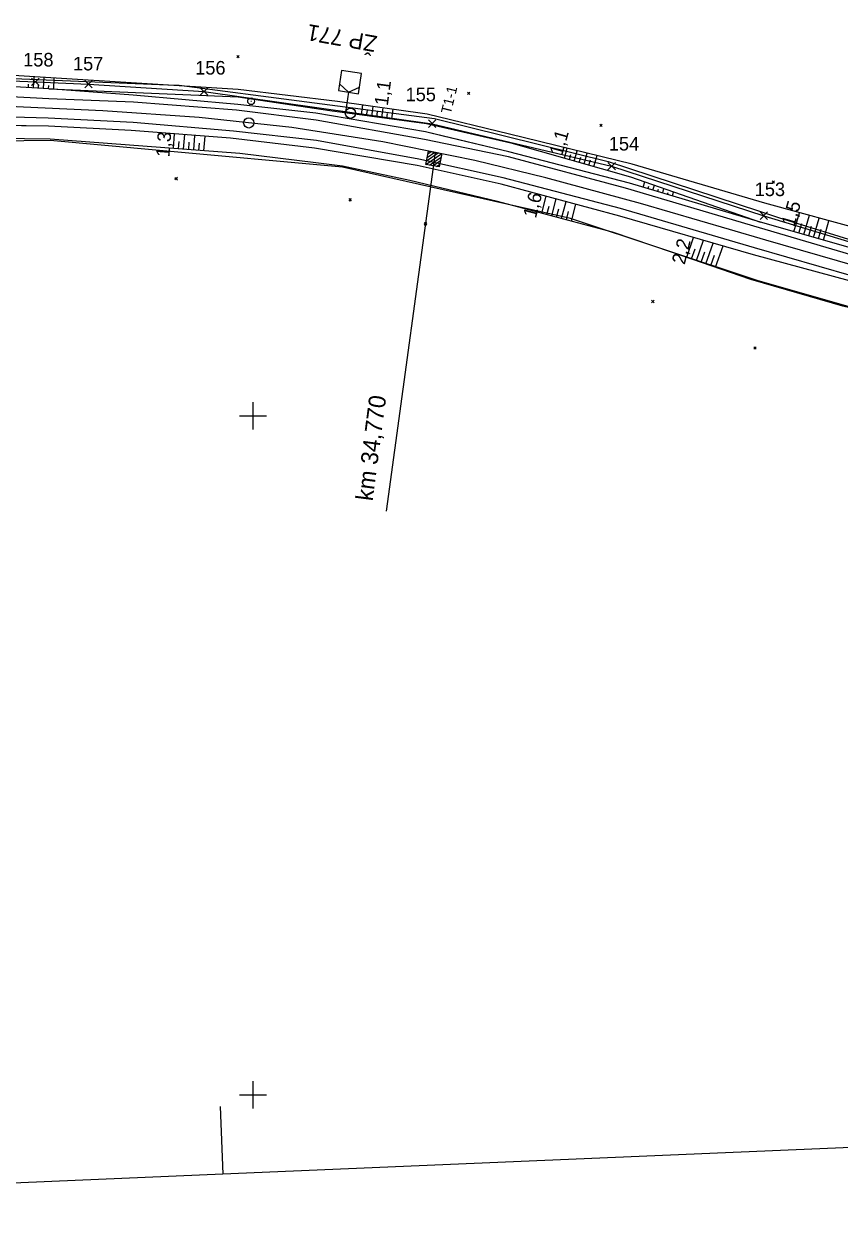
# Model space of a CAD drawing. Extents: x -806456 to -805395, y -1150847 to -1150506.
# Drawn here: x -805633.7 to -805513.6, y -1150820.6 to -1150642.3 of the extents above; entities that cross this region are included whole.
import ezdxf

# ---------------------------------------------------------------- set-up
doc = ezdxf.new("R2010")
doc.units = 0
for name, color, linetype in [('0381KM032-037P - Vrstva 1', 7, 'Continuous'), ('0381KM032-037P - Vrstva 3', 7, 'Continuous'), ('0381KM032-037P - Vrstva 4', 7, 'Continuous'), ('0381KM032-037P - Vrstva 48', 7, 'Continuous'), ('0381KM032-037P - Vrstva 49', 7, 'Continuous'), ('0381KM032-037P - Vrstva 7', 7, 'Continuous'), ('Default', 7, 'Continuous'), ('formát', 7, 'Continuous'), ('hran DP - hran DP', 7, 'Continuous'), ('krizky_1000 - Vrstva 1', 7, 'Continuous'), ('PSR_C2_2_Lomove_body_Vimperk - Vrstva 60', 7, 'Continuous'), ('PSR_C2_2_trasa_Vimperk - Kabelová trasa', 7, 'Continuous'), ('vyt_sit - ohrožené', 7, 'Continuous')]:
    doc.layers.add(name, color=color, linetype=linetype)

msp = doc.modelspace()

# ---------------------------------------------------------------- linework, layer by layer
at = {"layer": '0381KM032-037P - Vrstva 1'}
for points in [[(-805607.93, -1150656.05), (-805622.11, -1150655.05), (-805635.9, -1150654.45), (-805647.61, -1150654.06)], [(-805567.32, -1150662.37), (-805580.89, -1150659.62), (-805594.29, -1150657.54), (-805607.93, -1150656.05)], [(-805529.81, -1150672.54), (-805542.91, -1150668.73), (-805556.85, -1150664.92), (-805567.32, -1150662.37)], [(-805499.4, -1150681.08), (-805511.35, -1150677.89), (-805524.48, -1150674.12), (-805529.81, -1150672.54)]]:
    msp.add_lwpolyline(points, dxfattribs=at)
at = {"layer": '0381KM032-037P - Vrstva 3'}
for p, q in [((-805573.17, -1150661.19), (-805580.37, -1150714.04)), ((-805574.52, -1150662.97), (-805572.18, -1150661.37)), ((-805574.42, -1150662.44), (-805572.71, -1150661.27)), ((-805574.32, -1150661.92), (-805573.23, -1150661.17)), ((-805574.23, -1150661.4), (-805573.75, -1150661.08)), ((-805574, -1150663.06), (-805572.28, -1150661.89)), ((-805573.48, -1150663.16), (-805572.38, -1150662.41)), ((-805572.96, -1150663.26), (-805572.48, -1150662.93))]:
    msp.add_line(p, q, dxfattribs=at)
msp.add_lwpolyline([(-805574.15, -1150661), (-805572.18, -1150661.37), (-805572.55, -1150663.34), (-805574.52, -1150662.97)], close=True, dxfattribs=at)
at = {"layer": '0381KM032-037P - Vrstva 4'}
for points in [[(-805485.85, -1150681.76), (-805498.96, -1150678.92), (-805510.6, -1150675.66), (-805525.22, -1150671.48), (-805544.53, -1150665.72), (-805562.31, -1150661.11), (-805574.56, -1150658.15), (-805590.74, -1150655.42), (-805602.22, -1150654.14), (-805617.62, -1150652.74), (-805630.08, -1150651.83), (-805647.65, -1150650.8), (-805688.26, -1150650.5)], [(-805423.97, -1150686.92), (-805425.51, -1150687.49), (-805433.17, -1150688.49), (-805447.58, -1150687.79), (-805460.54, -1150686.52), (-805473.03, -1150684.97), (-805486, -1150682.53), (-805499.06, -1150679.64), (-805510.93, -1150676.58), (-805525.41, -1150672.29), (-805545.14, -1150666.47), (-805562.36, -1150661.85), (-805574.71, -1150659.28), (-805590.7, -1150656.46), (-805602.42, -1150654.96), (-805617.57, -1150653.8), (-805630.08, -1150653.28), (-805647.6, -1150652.35), (-805687.98, -1150651.47)], [(-805425.98, -1150691.47), (-805433.13, -1150691.22), (-805447.47, -1150690.71), (-805460.74, -1150689.57), (-805473.54, -1150687.87), (-805486.2, -1150685.62), (-805499.7, -1150682.42), (-805511.82, -1150679.35), (-805526.11, -1150675.23), (-805545.84, -1150669.48), (-805563.16, -1150664.96), (-805575.57, -1150662.2), (-805590.62, -1150659.46), (-805602.86, -1150658.06), (-805617.64, -1150656.78), (-805630.16, -1150656.16), (-805647.73, -1150655.65), (-805688.15, -1150654.42)], [(-805425.41, -1150692.47), (-805425.98, -1150691.47), (-805433.11, -1150692.35), (-805447.61, -1150691.82), (-805460.9, -1150690.59), (-805473.67, -1150688.98), (-805486.26, -1150686.57), (-805500.08, -1150683.65), (-805512.15, -1150680.12), (-805526.27, -1150676.26), (-805545.98, -1150670.57), (-805563.42, -1150665.87), (-805575.79, -1150663.12), (-805590.93, -1150660.59), (-805603.28, -1150659.09), (-805617.92, -1150657.97), (-805630.11, -1150657.32), (-805646.66, -1150657.1), (-805648.58, -1150657.2), (-805687.42, -1150655.93)]]:
    msp.add_lwpolyline(points, dxfattribs=at)
at = {"layer": '0381KM032-037P - Vrstva 48'}
for p, q in [((-805633.08, -1150651.65), (-805633.05, -1150651.16)), ((-805632.33, -1150651.7), (-805632.24, -1150650.05)), ((-805631.59, -1150651.74), (-805631.56, -1150651.25)), ((-805630.84, -1150651.79), (-805630.74, -1150650.15)), ((-805630.09, -1150651.83), (-805630.06, -1150651.34)), ((-805629.34, -1150651.86), (-805629.27, -1150650.24)), ((-805583.99, -1150655.65), (-805583.8, -1150654.21)), ((-805583.25, -1150655.75), (-805583.15, -1150655.03)), ((-805582.5, -1150655.85), (-805582.31, -1150654.42)), ((-805581.02, -1150656.05), (-805580.83, -1150654.64)), ((-805579.53, -1150656.25), (-805579.34, -1150654.85)), ((-805581.76, -1150655.95), (-805581.66, -1150655.24)), ((-805580.27, -1150656.15), (-805580.18, -1150655.44)), ((-805611.7, -1150660.6), (-805611.54, -1150658.46)), ((-805610.21, -1150660.72), (-805610.04, -1150658.57)), ((-805610.96, -1150660.66), (-805610.87, -1150659.59)), ((-805609.46, -1150660.78), (-805609.38, -1150659.7)), ((-805608.71, -1150660.83), (-805608.55, -1150658.69)), ((-805607.96, -1150660.89), (-805607.88, -1150659.82)), ((-805607.21, -1150660.95), (-805607.05, -1150658.8)), ((-805554.11, -1150662.05), (-805553.7, -1150660.58)), ((-805553.39, -1150662.26), (-805553.18, -1150661.51)), ((-805552.67, -1150662.46), (-805552.24, -1150660.94)), ((-805551.95, -1150662.67), (-805551.73, -1150661.89)), ((-805551.23, -1150662.87), (-805550.78, -1150661.3)), ((-805549.79, -1150663.28), (-805549.32, -1150661.66)), ((-805550.51, -1150663.08), (-805550.28, -1150662.28)), ((-805542.53, -1150666.31), (-805542.3, -1150665.55)), ((-805541.81, -1150666.53), (-805541.7, -1150666.16)), ((-805541.09, -1150666.74), (-805540.88, -1150666.04)), ((-805540.37, -1150666.96), (-805540.27, -1150666.62)), ((-805539.65, -1150667.17), (-805539.46, -1150666.53)), ((-805538.93, -1150667.39), (-805538.84, -1150667.08)), ((-805538.21, -1150667.6), (-805538.04, -1150667.03)), ((-805557.45, -1150670.15), (-805556.79, -1150667.66)), ((-805556.72, -1150670.35), (-805556.39, -1150669.1)), ((-805556, -1150670.54), (-805555.34, -1150668.05)), ((-805554.55, -1150670.93), (-805553.89, -1150668.44)), ((-805553.1, -1150671.31), (-805552.44, -1150668.83)), ((-805555.28, -1150670.73), (-805554.95, -1150669.49)), ((-805553.83, -1150671.12), (-805553.5, -1150669.88)), ((-805520.31, -1150672.89), (-805519.5, -1150670.07)), ((-805518.86, -1150673.3), (-805518.05, -1150670.46)), ((-805517.42, -1150673.71), (-805516.6, -1150670.86)), ((-805519.58, -1150673.09), (-805519.18, -1150671.68)), ((-805518.14, -1150673.5), (-805517.73, -1150672.08)), ((-805516.7, -1150673.92), (-805516.29, -1150672.49)), ((-805515.98, -1150674.12), (-805515.16, -1150671.25)), ((-805536.11, -1150676.64), (-805535.09, -1150673.71)), ((-805534.69, -1150677.13), (-805533.65, -1150674.13)), ((-805533.28, -1150677.62), (-805532.21, -1150674.54)), ((-805535.4, -1150676.88), (-805534.89, -1150675.4)), ((-805533.99, -1150677.38), (-805533.46, -1150675.85)), ((-805532.57, -1150677.87), (-805532.03, -1150676.31)), ((-805531.86, -1150678.11), (-805530.76, -1150674.96))]:
    msp.add_line(p, q, dxfattribs=at)
at = {"layer": '0381KM032-037P - Vrstva 49'}
for p, q in [((-805602.01, -1150646.92), (-805602.36, -1150647.28)), ((-805602.36, -1150646.92), (-805602.01, -1150647.28)), ((-805568.05, -1150652.69), (-805568.41, -1150652.34)), ((-805568.05, -1150652.34), (-805568.41, -1150652.69)), ((-805548.54, -1150657.39), (-805548.89, -1150657.04)), ((-805548.54, -1150657.04), (-805548.89, -1150657.39)), ((-805611.13, -1150664.88), (-805611.48, -1150665.23)), ((-805611.48, -1150664.88), (-805611.12, -1150665.23)), ((-805523.18, -1150665.72), (-805523.53, -1150665.37)), ((-805523.18, -1150665.37), (-805523.53, -1150665.72)), ((-805585.52, -1150668), (-805585.87, -1150668.36)), ((-805585.87, -1150668), (-805585.52, -1150668.36)), ((-805574.41, -1150671.9), (-805574.76, -1150671.55)), ((-805574.41, -1150671.55), (-805574.76, -1150671.9)), ((-805540.92, -1150683.33), (-805541.28, -1150682.98)), ((-805540.92, -1150682.98), (-805541.28, -1150683.33)), ((-805525.86, -1150690.16), (-805526.21, -1150689.81)), ((-805525.86, -1150689.81), (-805526.21, -1150690.16))]:
    msp.add_line(p, q, dxfattribs=at)
for points in [[(-805602.19, -1150651.94), (-805630.54, -1150650.16), (-805647.04, -1150649.14), (-805681.66, -1150649.9), (-805688.26, -1150650.5)], [(-805423.97, -1150686.92), (-805433.1, -1150687.91), (-805447.34, -1150686.91), (-805460.49, -1150686.09), (-805485.85, -1150681.76), (-805498.96, -1150678.92), (-805510.6, -1150675.66), (-805525.22, -1150671.48), (-805544.53, -1150665.72), (-805562.31, -1150661.11), (-805571.99, -1150658.79), (-805574.56, -1150658.15), (-805590.74, -1150655.42), (-805602.22, -1150654.14), (-805617.62, -1150652.74), (-805630.08, -1150651.83), (-805647.65, -1150650.8), (-805688.26, -1150650.5)], [(-805630.08, -1150651.83), (-805602.16, -1150653.02), (-805588.68, -1150655.02)], [(-805424.36, -1150683.57), (-805432.74, -1150683.28), (-805452.35, -1150683.91), (-805462.43, -1150682.34), (-805472.3, -1150680.9), (-805485.84, -1150678.15), (-805509.51, -1150672.79), (-805524.62, -1150668.67), (-805544.15, -1150662.92), (-805562.19, -1150658.51), (-805574.34, -1150655.56), (-805587.56, -1150653.68), (-805602.19, -1150651.94)], [(-805588.68, -1150655.02), (-805574.43, -1150656.93), (-805562.03, -1150659.8), (-805544.41, -1150664.81), (-805525.22, -1150671.48)], [(-805425.41, -1150692.47), (-805425.98, -1150691.47), (-805433.11, -1150692.35), (-805447.61, -1150691.82), (-805460.9, -1150690.59), (-805473.67, -1150688.98), (-805486.26, -1150686.57), (-805500.08, -1150683.65), (-805512.15, -1150680.12), (-805526.27, -1150676.26), (-805545.98, -1150670.57), (-805563.42, -1150665.87), (-805575.79, -1150663.12), (-805590.93, -1150660.59), (-805603.28, -1150659.09), (-805617.92, -1150657.97), (-805630.11, -1150657.32), (-805646.15, -1150657.11), (-805646.27, -1150657.1), (-805646.57, -1150657.13), (-805646.66, -1150657.1), (-805648.58, -1150657.2), (-805687.42, -1150655.93)], [(-805428.8, -1150698.61), (-805426.99, -1150695.45), (-805434.79, -1150695.76), (-805452.59, -1150694.8), (-805474.79, -1150691.73), (-805486.9, -1150690.07), (-805513.13, -1150683.83), (-805526.69, -1150679.91), (-805538.18, -1150675.92), (-805547.05, -1150672.92), (-805563.97, -1150668.42), (-805576.87, -1150665.35), (-805586.81, -1150663.24), (-805590.73, -1150662.74), (-805601.92, -1150661.35), (-805629.88, -1150659.22), (-805648.74, -1150658.99), (-805687.58, -1150660.02)]]:
    msp.add_lwpolyline(points, dxfattribs=at)
at = {"layer": '0381KM032-037P - Vrstva 7'}
for p, q in [((-805585.93, -1150652.33), (-805586.39, -1150655.29)), ((-805600.32, -1150653.66), (-805600.22, -1150653.66)), ((-805586.89, -1150655.21), (-805585.9, -1150655.37))]:
    msp.add_line(p, q, dxfattribs=at)
for points in [[(-805585.93, -1150652.33), (-805584.45, -1150652.56), (-805583.99, -1150649.59), (-805586.96, -1150649.13), (-805587.42, -1150652.1), (-805585.93, -1150652.33)], [(-805587.26, -1150651.11), (-805585.93, -1150652.33), (-805584.3, -1150651.57)]]:
    msp.add_lwpolyline(points, dxfattribs=at)
for centre, radius in [((-805600.27, -1150653.66), 0.5), ((-805600.62, -1150656.85), 0.75)]:
    msp.add_circle(centre, radius, dxfattribs=at)
at = {"layer": 'formát'}
for p, q in [((-805604.84, -1150801.71), (-805604.42, -1150811.7)), ((-805394.61, -1150802.8), (-805604.42, -1150811.7)), ((-805604.42, -1150811.7), (-805814.23, -1150820.61))]:
    msp.add_line(p, q, dxfattribs=at)
at = {"layer": 'hran DP - hran DP'}
for p, q in [((-805645.21, -1150649.93), (-805611.34, -1150651.29)), ((-805611.34, -1150651.29), (-805610.86, -1150651.29)), ((-805610.86, -1150651.29), (-805573.24, -1150656.2)), ((-805573.24, -1150656.2), (-805547.66, -1150662.54)), ((-805629.87, -1150659.45), (-805660.75, -1150659.79)), ((-805613.77, -1150660.92), (-805629.87, -1150659.45)), ((-805586.79, -1150663.39), (-805613.77, -1150660.92)), ((-805553.22, -1150670.95), (-805586.79, -1150663.39)), ((-805547.66, -1150662.54), (-805525.39, -1150669.85)), ((-805525.6, -1150680.1), (-805553.22, -1150670.95)), ((-805525.39, -1150669.85), (-805522.57, -1150670.78)), ((-805522.57, -1150670.78), (-805505.56, -1150676.07)), ((-805492.06, -1150689.65), (-805525.6, -1150680.1))]:
    msp.add_line(p, q, dxfattribs=at)
at = {"layer": 'krizky_1000 - Vrstva 1'}
for points in [[(-805600, -1150698), (-805600, -1150702)], [(-805602, -1150700), (-805598, -1150700)], [(-805600, -1150798), (-805600, -1150802)], [(-805602, -1150800), (-805598, -1150800)]]:
    msp.add_lwpolyline(points, dxfattribs=at)
at = {"layer": 'PSR_C2_2_Lomove_body_Vimperk - Vrstva 60'}
for p, q in [((-805632.59, -1150651.36), (-805631.49, -1150650.26)), ((-805631.49, -1150651.36), (-805632.59, -1150650.26)), ((-805624.78, -1150651.68), (-805623.68, -1150650.58)), ((-805623.68, -1150651.68), (-805624.78, -1150650.58)), ((-805607.76, -1150652.76), (-805606.66, -1150651.66)), ((-805606.66, -1150652.76), (-805607.76, -1150651.66)), ((-805574.14, -1150657.52), (-805573.04, -1150656.42)), ((-805573.04, -1150657.52), (-805574.14, -1150656.42)), ((-805547.72, -1150663.76), (-805546.62, -1150662.66)), ((-805546.62, -1150663.76), (-805547.72, -1150662.66)), ((-805525.3, -1150671.07), (-805524.2, -1150669.97)), ((-805524.2, -1150671.07), (-805525.3, -1150669.97))]:
    msp.add_line(p, q, dxfattribs=at)
at = {"layer": 'PSR_C2_2_trasa_Vimperk - Kabelová trasa'}
for points in [[(-805647.01, -1150650.18), (-805632.04, -1150650.81), (-805624.23, -1150651.13)], [(-805624.23, -1150651.13), (-805607.21, -1150652.21), (-805573.59, -1150656.97), (-805547.17, -1150663.21), (-805524.75, -1150670.52), (-805510.68, -1150674.8), (-805497.62, -1150678.19), (-805486.72, -1150680.63), (-805475.31, -1150683.18), (-805461.35, -1150684.65), (-805443.05, -1150686.29), (-805422.27, -1150685.42)]]:
    msp.add_lwpolyline(points, dxfattribs=at)
at = {"layer": 'vyt_sit - ohrožené'}
msp.add_line((-805585.69, -1150655.42), (-805585.58, -1150655.42), dxfattribs=at)
msp.add_circle((-805585.64, -1150655.42), 0.756, dxfattribs=at)

# ---------------------------------------------------------------- texts
at = {"layer": '0381KM032-037P - Vrstva 3'}
for s, height, rotation, p in [('T1-1', 1.5, 76.1469, (-805570.87, -1150655.63)), ('km 34,770', 2.5, 82.5204, (-805582.38, -1150712.62))]:
    msp.add_text(s, height=height, rotation=rotation, dxfattribs=at).set_placement(p)
at = {"layer": '0381KM032-037P - Vrstva 48'}
for s, rotation, p in [('1,1', 82.3827, (-805580.14, -1150654.4)), ('1,3', 85.6488, (-805612.3, -1150661.94)), ('1,1', 74.1019, (-805554.47, -1150661.8)), ('1,6', 75.1245, (-805558.33, -1150670.98)), ('1,5', 74.0489, (-805520.28, -1150672.25)), ('2,2', 75.6961, (-805536.41, -1150677.81))]:
    msp.add_text(s, height=2, rotation=rotation, dxfattribs=at).set_placement(p)
at = {"layer": 'Default'}
for s, p in [('158', (-805633.84, -1150648.54)), ('157', (-805626.5, -1150649.12)), ('156', (-805608.5, -1150649.73)), ('155', (-805577.51, -1150653.65)), ('154', (-805547.58, -1150660.92)), ('153', (-805526.09, -1150667.63))]:
    msp.add_text(s, height=2, dxfattribs=at).set_placement(p)
at = {"layer": 'vyt_sit - ohrožené'}
msp.add_text('ŽP 771', height=2.4, rotation=170, dxfattribs=at).set_placement((-805581.59, -1150644.08))

doc.saveas('drawing.dxf')
